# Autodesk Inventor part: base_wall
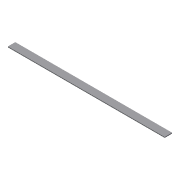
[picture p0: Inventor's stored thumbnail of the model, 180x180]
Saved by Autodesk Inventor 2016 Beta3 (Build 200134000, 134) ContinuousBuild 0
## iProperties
Created: 2016-03
Part Number: base_wall
Material: Generic
Document SubType Name: Modeling
Designer: Gaurav
Density: 1 g/cm^3
Appearance: Default
Author: Gaurav
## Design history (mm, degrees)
sketch "Sketch1"
  geometry: L1 (0, 0)-(3909.21, 0); L2 (3909.21, 0)-(3909.21, 185.369); L3 (3909.21, 185.369)-(0, 185.369); L4 (0, 185.369)-(0, 0)
  constraints: 8 end point, 2 parallel, 1 horizontal, 1 perpendicular
extrude "Extrusion1" new body sketch "Sketch1" distance "d0" = 20; taper "d1" = 0 deg
body "Solid1"
